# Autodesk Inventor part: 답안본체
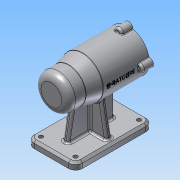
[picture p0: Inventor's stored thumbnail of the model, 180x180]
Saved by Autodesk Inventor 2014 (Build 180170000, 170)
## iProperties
Created: 2019-07
Part Number: 답안본체
Material: 알루미늄 6061
Document SubType Name: Modeling
Designer: net
Density: 2.71 g/cm^3
Appearance: 알루미늄 - 평지
Mass: 650.659 g
Surface Area: 656.887 cm^2
Volume: 240.096 cm^3
Author: net
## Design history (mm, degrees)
sketch "스케치1"
  geometry: L1 (-56, 0)-(56, 0); L2 (56, 21)-(56, 30); L3 (56, 30)-(-11, 30); L4 (-56, 0)-(-56, 15); L5 (-46, 25)-(-31, 25); L6 (-31, 25)-(-11, 30); L7 (56, 21)-(41, 21); L8 (41, 21)-(41, 21); L9 (38, 24)-(-10, 24); L10 (-13, 21)-(-13, 21); L11 (-13, 21)-(-24.7, 21); L12 (-25, 20.7)-(-25, 17.5); L13 (-25, 17.5)-(-42.7, 17.5); L14 (-43, 17.2)-(-43, 16); L15 (-43, 16)-(-46.7, 16); L16 (-47, 15.7)-(-47, 10.5); L17 (-47, 10.5)-(-47, 10.5); L18 (-50, 7.5)-(-50, 0); A1 r 10 centre (-46, 15) between (-46, 25) and (-56, 15); A2 r 3 centre (-47, 7.5) between (-47, 10.5) and (-50, 7.5); A3 r 3 centre (-10, 21) between (-10, 24) and (-13, 21); A4 r 3 centre (38, 21) between (41, 21) and (38, 24); A5 r 0.3 centre (-46.7, 15.7) between (-46.7, 16) and (-47, 15.7); A6 r 0.3 centre (-42.7, 17.2) between (-42.7, 17.5) and (-43, 17.2); A7 r 0.3 centre (-24.7, 20.7) between (-24.7, 21) and (-25, 20.7); 9 further points
  constraints: 36 end point, 15 perpendicular, 15 point on line, 14 point on circle, 14 tangent, 7 centre point, 4 equal radius, 1 coincident, 1 horizontal, 1 midpoint, 1 parallel
  dimensions: "d0" = 112 distance of L1.start L1.end; "d1" = 42 diameter of L2.start L1; "d2" = 60 diameter of L2.end L1; "d3" = 67 distance of L2.end L3.end; "d4" = 25 distance of L1.start point (-56, 25); "d5" = 25 distance of point (-56, 25) L5.end; "d6" = 45 horizontal distance of point (-56, 25) L3.end; "d7" = 10 radius of A1; "d8" = 15 distance of L2.start L7.end; "d9" = 48 diameter of point (41, 24) L1; "d10" = 54 distance of point (41, 24) point (-13, 24); "d11" = 42 diameter of L10.end L1; "d12" = 12 distance of L10.end point (-25, 21); "d13" = 35 diameter of L12.end L1; "d14" = 18 distance of L12.end point (-43, 17.5); "d15" = 32 diameter of L14.end L1; "d16" = 4 distance of L14.end point (-47, 16); "d17" = 21 diameter of L16.end L1; "d18" = 3 distance of L16.end point (-50, 10.5); "d19" = 3 radius of A2; "d20" = 0.3 radius of A5
revolve "회전1" sketch "스케치1" stored, may be unused: angle "d21" = 90 deg
node "작업 평면1"
sketch "스케치2"
  geometry: C1 r 21 at (0, 0) reference; A1 r 30 centre (0, 0) between (0, 30) and (-5.97, 29.4) reference; A2 r 6 centre (0, 30) between (5.97, 29.4) and (-5.97, 29.4); 2 further points
  constraints: 5 point on circle, 2 vertical alignment, 1 centre point, 1 coincident, 2 other
  dimensions: "d23" = 12 diameter of A2
extrude "돌출1" join sketch "스케치2" distance "d24" = 16; taper "d25" = 0 deg
fillet "모깎기1" dims "d29" = 3
fillet "모깎기2" dims "d30" = 1
node "작업 평면2"
sketch "스케치3"
  geometry: L1 (35, -56)-(-35, -56); L2 (-35, -56)-(-35, 56); L3 (-35, 56)-(35, 56); L4 (35, 56)-(35, -56); L5 (35, -56)-(-35, 56); L6 (-35, -56)-(35, 56); 1 further point
  constraints: 12 end point, 2 midpoint, 2 parallel, 1 horizontal, 1 perpendicular
  dimensions: "d32" = 70 distance of L2.end L3.end; "d33" = 112 distance of L1.end L2.end
extrude "돌출2" join sketch "스케치3" distance "d34" = 10; taper "d35" = 0 deg
fillet "모깎기3" dims "d36" = 10
chamfer "모따기1" distance "d37" = 3; stored, may be unused: second distance "d38" = 2, angle "d39" = 45 deg
sketch "스케치4"
  geometry: L1 (25, -53)-(-25, -53) reference; L2 (-4, 31)-(-4, -36); L3 (-4, -36)-(4, -36); L4 (4, -36)-(4, 31); L5 (4, 31)-(-4, 31); L6 (-25, 56)-(25, 56) reference; L7 (-25, -56)-(25, -56) reference; L8 (-28, 4)-(28, 4); L9 (28, 4)-(28, -4); L10 (28, -4)-(-28, -4); L11 (-28, -4)-(-28, 4); L12 (35, -46)-(35, 46) reference; L13 (-35, 46)-(-35, -46) reference; 3 further points
  constraints: 16 end point, 5 parallel, 3 perpendicular, 2 midpoint, 1 horizontal alignment, 1 vertical alignment
  dimensions: "d40" = 25 distance between parallel lines of L6 L5; "d41" = 20 distance between parallel lines of L7 L3; "d42" = 8 distance between parallel lines of L2 L4; "d43" = 7 distance between parallel lines of L12 L9; "d44" = 7 distance between parallel lines of L13 L11; "d45" = 8 distance between parallel lines of L8 L10
extrude "돌출3" join sketch "스케치4" stored distance "d46" = 10; taper "d47" = 0 deg
feature "면 기울기1" dims angle "d48" = 10 deg
feature "면 기울기2" dims angle "d49" = 10 deg
feature "면 기울기3" dims angle "d50" = 10 deg
fillet "모깎기4" dims "d51" = 3
fillet "모깎기5" dims "d52" = 3
fillet "모깎기6" dims "d53" = 3
sketch "스케치5"
  geometry: C1 r 3 at (-25, 46); C2 r 3 at (25, 46); C3 r 3 at (25, -46); C4 r 3 at (-25, -46); A1 r 7 centre (25, 46) between (32, 46) and (25, 53) reference; A2 r 7 centre (-25, 46) between (-25, 53) and (-32, 46) reference; A3 r 7 centre (-25, -46) between (-32, -46) and (-25, -53) reference; A4 r 7 centre (25, -46) between (25, -53) and (32, -46) reference; 1 further point
  constraints: 4 centre point, 4 coincident
  dimensions: "d54" = 6 diameter of C1; "d55" = 6 diameter of C2; "d56" = 6 diameter of C3; "d57" = 6 diameter of C4
extrude "돌출4" cut sketch "스케치5" distance "d58" = 10; taper "d59" = 0 deg
fillet "모깎기7" dims "d60" = 3
chamfer "모따기2" distance "d61" = 1; stored, may be unused: second distance "d62" = 2, angle "d63" = 45 deg
sketch "스케치6"
  geometry: A1 r 6 centre (30, -30) between (30.171, -35.998) and (30.171, -24.002) reference; A2 r 6 centre (0, 0) between (5.998, 0.171) and (-5.998, 0.171) reference; A3 r 6 centre (-30, -30) between (-30.171, -24.002) and (-30.171, -35.998) reference; A4 r 6 centre (0, -60) between (-5.998, -60.171) and (5.998, -60.171) reference; 4 further points
  constraints: 4 coincident
hole "구멍1" sketch "스케치6" at (0, 0), (30, -30), (0, -60), (-30, -30) diameter "d64" = 3.242; stored, may be unused: countersink angle "d68" = 90 deg, drill point angle "d70" = 118 deg; dims "d65" = 8, "d66" = 4, "d67" = 2, "d69" = 11
node "작업 평면3"
sketch "스케치7"
  geometry: L1 (33.5, 30.171)-(33.5, 36) reference; 2 further points
  constraints: 1 horizontal alignment, 1 other
  dimensions: "d71" = 42 distance from line of L1 point (-8.5, 0)
feature "엠보싱1" sketch "스케치7" dims "d0" = 112, "d1" = 42, "d2" = 60, "d3" = 67, "d4" = 25, "d5" = 25, "d6" = 45, "d7" = 10, "d8" = 15, "d9" = 48, "d10" = 54, "d11" = 42, "d12" = 12, "d13" = 35, "d14" = 18, "d15" = 32, "d16" = 4, "d17" = 21, "d18" = 3, "d19" = 3, "d20" = 0.3, "d72" = 0.5, "d73" = 0
node "솔리드1"
pattern_circular "원형 패턴1" dims angle "d27" = 360 deg
node "투영된 루프1"
other parameters: "d22" = 56
